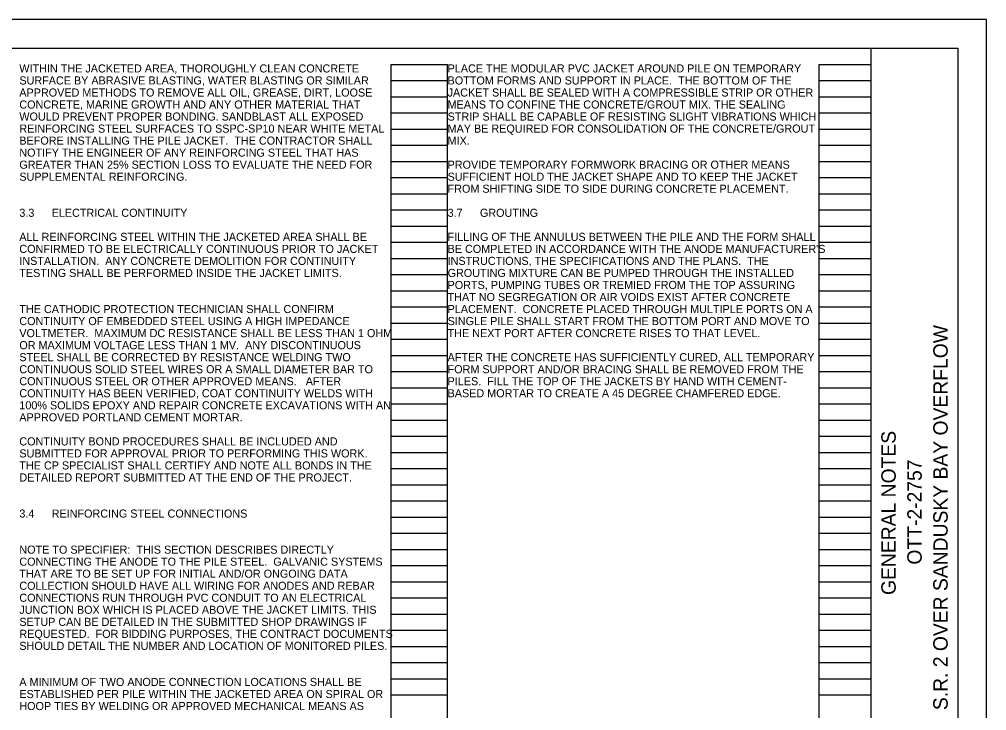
# Model space of a CAD drawing. Extents: x -0.5 to 34, y 0 to 22.
# Drawn here: x 17.24 to 34, y 10.03 to 22 of the extents above; entities that cross this region are included whole.
import ezdxf

# ---------------------------------------------------------------- set-up
doc = ezdxf.new("R2010")
doc.units = 0
for name, color, linetype in [('SH_Border', 7, 'Continuous'), ('SH_Cut_Line', 7, 'Continuous'), ('SH_Data', 7, 'Continuous'), ('SH_Text', 7, 'Continuous')]:
    doc.layers.add(name, color=color, linetype=linetype)

msp = doc.modelspace()

# ---------------------------------------------------------------- linework, layer by layer
at = {"layer": 'SH_Border'}
msp.add_line((32, 0.5), (32, 21.5), dxfattribs=at)
msp.add_lwpolyline([(1.5, 21.5), (33.5, 21.5), (33.5, 0.5), (1.5, 0.5)], close=True, dxfattribs=at)
at = {"layer": 'SH_Cut_Line'}
msp.add_lwpolyline([(0, 0), (34, 0), (34, 22), (0, 22)], close=True, dxfattribs=at)
at = {"layer": 'SH_Data'}
for p, q in [((23.68, 1.06), (23.68, 21.22)), ((23.68, 21.22), (24.66, 21.22)), ((24.66, 1.06), (24.66, 21.22)), ((31.1, 1.06), (31.1, 21.22)), ((31.1, 21.22), (32, 21.22)), ((32, 1.06), (32, 21.22)), ((23.68, 20.94), (24.66, 20.94)), ((31.1, 20.94), (32, 20.94)), ((23.68, 20.66), (24.66, 20.66)), ((31.1, 20.66), (32, 20.66)), ((23.68, 20.38), (24.66, 20.38)), ((31.1, 20.38), (32, 20.38)), ((23.68, 20.1), (24.66, 20.1)), ((31.1, 20.1), (32, 20.1)), ((23.68, 19.82), (24.66, 19.82)), ((31.1, 19.82), (32, 19.82)), ((23.68, 19.54), (24.66, 19.54)), ((31.1, 19.54), (32, 19.54)), ((23.68, 19.26), (24.66, 19.26)), ((31.1, 19.26), (32, 19.26)), ((23.68, 18.98), (24.66, 18.98)), ((31.1, 18.98), (32, 18.98)), ((23.68, 18.7), (24.66, 18.7)), ((31.1, 18.7), (32, 18.7)), ((23.68, 18.42), (24.66, 18.42)), ((31.1, 18.42), (32, 18.42)), ((23.68, 18.14), (24.66, 18.14)), ((31.1, 18.14), (32, 18.14)), ((23.68, 17.86), (24.66, 17.86)), ((31.1, 17.86), (32, 17.86)), ((23.68, 17.58), (24.66, 17.58)), ((31.1, 17.58), (32, 17.58)), ((23.68, 17.3), (24.66, 17.3)), ((31.1, 17.3), (32, 17.3)), ((23.68, 17.02), (24.66, 17.02)), ((31.1, 17.02), (32, 17.02)), ((23.68, 16.74), (24.66, 16.74)), ((31.1, 16.74), (32, 16.74)), ((23.68, 16.46), (24.66, 16.46)), ((31.1, 16.46), (32, 16.46)), ((23.68, 16.18), (24.66, 16.18)), ((31.1, 16.18), (32, 16.18)), ((23.68, 15.9), (24.66, 15.9)), ((31.1, 15.9), (32, 15.9)), ((23.68, 15.62), (24.66, 15.62)), ((31.1, 15.62), (32, 15.62)), ((23.68, 15.34), (24.66, 15.34)), ((31.1, 15.34), (32, 15.34)), ((23.68, 15.06), (24.66, 15.06)), ((31.1, 15.06), (32, 15.06)), ((23.68, 14.78), (24.66, 14.78)), ((31.1, 14.78), (32, 14.78)), ((23.68, 14.5), (24.66, 14.5)), ((31.1, 14.5), (32, 14.5)), ((23.68, 14.22), (24.66, 14.22)), ((31.1, 14.22), (32, 14.22)), ((23.68, 13.94), (24.66, 13.94)), ((31.1, 13.94), (32, 13.94)), ((23.68, 13.66), (24.66, 13.66)), ((31.1, 13.66), (32, 13.66)), ((23.68, 13.38), (24.66, 13.38)), ((31.1, 13.38), (32, 13.38)), ((23.68, 13.1), (24.66, 13.1)), ((31.1, 13.1), (32, 13.1)), ((23.68, 12.82), (24.66, 12.82)), ((31.1, 12.82), (32, 12.82)), ((23.68, 12.54), (24.66, 12.54)), ((31.1, 12.54), (32, 12.54)), ((23.68, 12.26), (24.66, 12.26)), ((31.1, 12.26), (32, 12.26)), ((23.68, 11.98), (24.66, 11.98)), ((31.1, 11.98), (32, 11.98)), ((23.68, 11.7), (24.66, 11.7)), ((31.1, 11.7), (32, 11.7)), ((23.68, 11.42), (24.66, 11.42)), ((31.1, 11.42), (32, 11.42)), ((23.68, 11.14), (24.66, 11.14)), ((31.1, 11.14), (32, 11.14)), ((23.68, 10.86), (24.66, 10.86)), ((31.1, 10.86), (32, 10.86)), ((23.68, 10.58), (24.66, 10.58)), ((31.1, 10.58), (32, 10.58)), ((23.68, 10.3), (24.66, 10.3)), ((31.1, 10.3), (32, 10.3))]:
    msp.add_line(p, q, dxfattribs=at)

# ---------------------------------------------------------------- texts
for s, p in [('S.R. 2 OVER SANDUSKY BAY OVERFLOW', (33.325, 10.037)), ('GENERAL NOTES', (32.425, 12.031)), ('OTT-2-2757', (32.875, 12.557))]:
    msp.add_text(s, height=0.25, rotation=90, dxfattribs=at).set_placement(p)
at = {"layer": 'SH_Text'}
for s, p in [('WITHIN THE JACKETED AREA, THOROUGHLY CLEAN CONCRETE ', (17.24, 21.08)), ('PLACE THE MODULAR PVC JACKET AROUND PILE ON TEMPORARY ', (24.66, 21.08)), ('SURFACE BY ABRASIVE BLASTING, WATER BLASTING OR SIMILAR ', (17.24, 20.872)), ('BOTTOM FORMS AND SUPPORT IN PLACE.  THE BOTTOM OF THE ', (24.66, 20.872)), ('APPROVED METHODS TO REMOVE ALL OIL, GREASE, DIRT, LOOSE ', (17.24, 20.663)), ('JACKET SHALL BE SEALED WITH A COMPRESSIBLE STRIP OR OTHER ', (24.66, 20.663)), ('CONCRETE, MARINE GROWTH AND ANY OTHER MATERIAL THAT ', (17.24, 20.455)), ('MEANS TO CONFINE THE CONCRETE/GROUT MIX. THE SEALING ', (24.66, 20.455)), ('WOULD PREVENT PROPER BONDING. SANDBLAST ALL EXPOSED ', (17.24, 20.247)), ('STRIP SHALL BE CAPABLE OF RESISTING SLIGHT VIBRATIONS WHICH ', (24.66, 20.247)), ('REINFORCING STEEL SURFACES TO SSPC-SP10 NEAR WHITE METAL ', (17.24, 20.038)), ('MAY BE REQUIRED FOR CONSOLIDATION OF THE CONCRETE/GROUT ', (24.66, 20.038)), ('BEFORE INSTALLING THE PILE JACKET.  THE CONTRACTOR SHALL ', (17.24, 19.83)), ('MIX.  ', (24.66, 19.83)), ('NOTIFY THE ENGINEER OF ANY REINFORCING STEEL THAT HAS ', (17.24, 19.622)), ('GREATER THAN 25% SECTION LOSS TO EVALUATE THE NEED FOR ', (17.24, 19.413)), ('PROVIDE TEMPORARY FORMWORK BRACING OR OTHER MEANS ', (24.66, 19.413)), ('SUPPLEMENTAL REINFORCING.', (17.24, 19.205)), ('SUFFICIENT HOLD THE JACKET SHAPE AND TO KEEP THE JACKET ', (24.66, 19.205)), ('FROM SHIFTING SIDE TO SIDE DURING CONCRETE PLACEMENT.  ', (24.66, 18.997)), ('3.3 ', (17.24, 18.58)), ('ELECTRICAL CONTINUITY', (17.8, 18.58)), ('3.7', (24.66, 18.58)), ('GROUTING', (25.22, 18.58)), ('ALL REINFORCING STEEL WITHIN THE JACKETED AREA SHALL BE ', (17.24, 18.163)), ('FILLING OF THE ANNULUS BETWEEN THE PILE AND THE FORM SHALL ', (24.66, 18.163)), ('CONFIRMED TO BE ELECTRICALLY CONTINUOUS PRIOR TO JACKET ', (17.24, 17.955)), ("BE COMPLETED IN ACCORDANCE WITH THE ANODE MANUFACTURER'S ", (24.66, 17.955)), ('INSTALLATION.  ANY CONCRETE DEMOLITION FOR CONTINUITY ', (17.24, 17.747)), ('INSTRUCTIONS, THE SPECIFICATIONS AND THE PLANS.  THE ', (24.66, 17.747)), ('TESTING SHALL BE PERFORMED INSIDE THE JACKET LIMITS. ', (17.24, 17.538)), ('GROUTING MIXTURE CAN BE PUMPED THROUGH THE INSTALLED ', (24.66, 17.538)), ('PORTS, PUMPING TUBES OR TREMIED FROM THE TOP ASSURING ', (24.66, 17.33)), ('THAT NO SEGREGATION OR AIR VOIDS EXIST AFTER CONCRETE ', (24.66, 17.121)), ('THE CATHODIC PROTECTION TECHNICIAN SHALL CONFIRM ', (17.24, 16.913)), ('PLACEMENT.  CONCRETE PLACED THROUGH MULTIPLE PORTS ON A ', (24.66, 16.913)), ('CONTINUITY OF EMBEDDED STEEL USING A HIGH IMPEDANCE ', (17.24, 16.705)), ('SINGLE PILE SHALL START FROM THE BOTTOM PORT AND MOVE TO ', (24.66, 16.705)), ('VOLTMETER.  MAXIMUM DC RESISTANCE SHALL BE LESS THAN 1 OHM ', (17.24, 16.496)), ('THE NEXT PORT AFTER CONCRETE RISES TO THAT LEVEL.  ', (24.66, 16.496)), ('OR MAXIMUM VOLTAGE LESS THAN 1 MV.  ANY DISCONTINUOUS ', (17.24, 16.288)), ('STEEL SHALL BE CORRECTED BY RESISTANCE WELDING TWO ', (17.24, 16.08)), ('AFTER THE CONCRETE HAS SUFFICIENTLY CURED, ALL TEMPORARY ', (24.66, 16.08)), ('CONTINUOUS SOLID STEEL WIRES OR A SMALL DIAMETER BAR TO ', (17.24, 15.871)), ('FORM SUPPORT AND/OR BRACING SHALL BE REMOVED FROM THE ', (24.66, 15.871)), ('CONTINUOUS STEEL OR OTHER APPROVED MEANS.   AFTER ', (17.24, 15.663)), ('PILES.  FILL THE TOP OF THE JACKETS BY HAND WITH CEMENT-', (24.66, 15.663)), ('CONTINUITY HAS BEEN VERIFIED, COAT CONTINUITY WELDS WITH ', (17.24, 15.455)), ('BASED MORTAR TO CREATE A 45 DEGREE CHAMFERED EDGE.', (24.66, 15.455)), ('100% SOLIDS EPOXY AND REPAIR CONCRETE EXCAVATIONS WITH AN ', (17.24, 15.246)), ('APPROVED PORTLAND CEMENT MORTAR.', (17.24, 15.038)), ('CONTINUITY BOND PROCEDURES SHALL BE INCLUDED AND ', (17.24, 14.621)), ('SUBMITTED FOR APPROVAL PRIOR TO PERFORMING THIS WORK.  ', (17.24, 14.413)), ('THE CP SPECIALIST SHALL CERTIFY AND NOTE ALL BONDS IN THE ', (17.24, 14.205)), ('DETAILED REPORT SUBMITTED AT THE END OF THE PROJECT.', (17.24, 13.996)), ('3.4', (17.24, 13.371)), ('REINFORCING STEEL CONNECTIONS', (17.8, 13.371)), ('NOTE TO SPECIFIER:  THIS SECTION DESCRIBES DIRECTLY ', (17.24, 12.746)), ('CONNECTING THE ANODE TO THE PILE STEEL.  GALVANIC SYSTEMS ', (17.24, 12.538)), ('THAT ARE TO BE SET UP FOR INITIAL AND/OR ONGOING DATA ', (17.24, 12.33)), ('COLLECTION SHOULD HAVE ALL WIRING FOR ANODES AND REBAR ', (17.24, 12.121)), ('CONNECTIONS RUN THROUGH PVC CONDUIT TO AN ELECTRICAL ', (17.24, 11.913)), ('JUNCTION BOX WHICH IS PLACED ABOVE THE JACKET LIMITS. THIS ', (17.24, 11.705)), ('SETUP CAN BE DETAILED IN THE SUBMITTED SHOP DRAWINGS IF ', (17.24, 11.496)), ('REQUESTED.  FOR BIDDING PURPOSES, THE CONTRACT DOCUMENTS ', (17.24, 11.288)), ('SHOULD DETAIL THE NUMBER AND LOCATION OF MONITORED PILES.', (17.24, 11.08)), ('A MINIMUM OF TWO ANODE CONNECTION LOCATIONS SHALL BE ', (17.24, 10.455)), ('ESTABLISHED PER PILE WITHIN THE JACKETED AREA ON SPIRAL OR ', (17.24, 10.246)), ('HOOP TIES BY WELDING OR APPROVED MECHANICAL MEANS AS ', (17.24, 10.038))]:
    msp.add_text(s, height=0.14, dxfattribs=at).set_placement(p)

doc.saveas('drawing.dxf')
